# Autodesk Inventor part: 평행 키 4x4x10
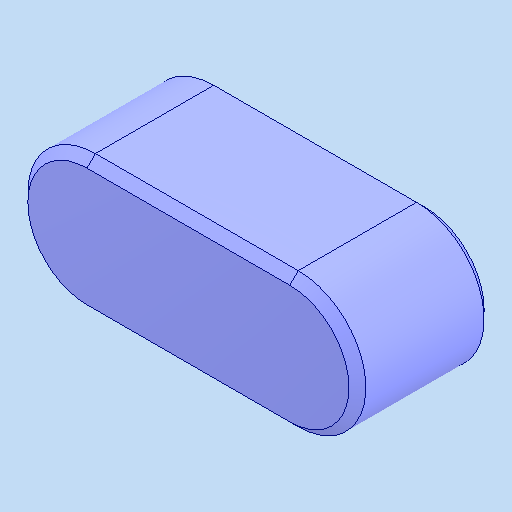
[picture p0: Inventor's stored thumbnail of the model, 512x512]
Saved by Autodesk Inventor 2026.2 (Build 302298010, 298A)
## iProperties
Created: 2026-08
Part Number: 평행 키 4x4x10
Material: 강철, 연강
Description: 키 및 해당 키홈
Document SubType Name: Modeling
Designer: PC-2-06
Density: 7.85 g/cm^3
Appearance: 기본값
Author: jhkim
Sending System: Autodesk Inventor 2027
Preprocessor: ST-DEVELOPER v20.1
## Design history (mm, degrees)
feature "Solid1"
node "솔리드1"
